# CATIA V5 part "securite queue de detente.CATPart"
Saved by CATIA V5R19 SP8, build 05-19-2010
Part number: sécurité queue de détente
Bounding box of the stored display mesh (mm): x 0 to 2, y -9.12 to 8.514, z -12.396 to 5.442
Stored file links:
  C:\Users\Arthur\Desktop\Catia parts\GLOCK\Poignée\securite queue de detente.CATPart
  C:\Users\Arthur\Desktop\Catia parts\GLOCK\Poignée\queue de detente.CATPart
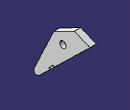
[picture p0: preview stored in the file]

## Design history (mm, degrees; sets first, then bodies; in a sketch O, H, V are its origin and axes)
Set1
  Sketch1 on yz-plane, origin (0, 0, 0), H (0, 1, 0), V (0, 0, 1)
    circle A1 centre (0, 0) radius 1
    point P1 (0.9998, -0.0212)
    line L1 (-2.8713, 2.1187) -> (-9.032, -10.9778)
    point P3 (-8.6694, -10.207)
    point P4 (-4.0642, -8.8361)
    line L2 (-4.0642, -8.8361) -> (-4.4128, -8.4777)
    line L3 (-4.4128, -8.4777) -> (-2.9792, -7.0831)
    point P6 (-2.9792, -7.0831)
    line L4 (-2.9792, -7.0831) -> (-2.6306, -7.4415)
    point P7 (-2.9792, -7.0831)
    point P8 (-2.6306, -7.4415)
    axis line L5 (-3.3947, -8.1848) -> (-0.2818, -5.1568)
    line L6 (-4.0642, -8.8361) -> (-7.436, -12.1159)
    arc A2 centre (-8.1306, -11.4018) radius 0.9962 from (-7.436, -12.1159) to (-9.032, -10.9778) cw
    line L7 (-2.6306, -7.4415) -> (6.4251, 1.3672)
    line L8 (3.6545, 5.442) -> (8.5143, 3.3993)
    point P15 (3.6545, 5.442)
    point P16 (8.5143, 3.3993)
    line L9 (8.5143, 3.3993) -> (6.4251, 1.3672)
    line L10 (3.6545, 5.442) -> (-2.8713, 2.1187)
    point P17 (3.6545, 5.442)
    radius A1 = 1
    radius A2 = 0.9962
    distance L2 A2 = 5.7
    length L2 = 0.5
    length L3 = 2
    distance A1 L1 = 2.5
    distance L7 A1 = 2.5
    distance O A2 = 15
    distance P16 A2 = 23.27
    coincidence: A1 P1, P7 P6, P8 L5, P4 L5, L1 P3, P15 P17, L9 L7
    perpendicularity: L3 L2
    parallelism: L4 L2, L5 L3, L6 L5, L7 L6
    tangency: A2 L6, A2 L1
    fix: P15
Body1 (main body)
  Pad1: profile Sketch1, direction (1, 0, 0), length 2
